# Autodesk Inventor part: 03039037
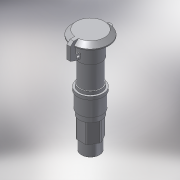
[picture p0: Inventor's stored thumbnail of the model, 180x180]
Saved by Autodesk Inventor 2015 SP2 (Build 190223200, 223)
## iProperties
Created: 2017-06
Part Number: 03039037
Material: PVC-Piping
Description: PLASSON QUICK COUPLING VALVE 3/4"
Document SubType Name: Modeling
Designer: KIM
Mass: 160.732 g
Surface Area: 217.168 cm^2
Volume: 114.809 cm^3
Density: 1.4 g/cm^3
Appearance: Smooth - White
Author: KIM
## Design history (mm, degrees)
derived "03039.ipt"
feature "Solid1::03039.ipt"
tag "TaggingFeature1"
body "Solid1"
other parameters: "d1" = 152, "d23" = 17, "d24" = 45.6, "d25" = 53.2, "d26" = 76, "d27" = 80.56, "d28" = 85.12, "d29" = 118.56, "d32" = 144.4, "d33" = 145.92, "d34" = 26.441, "d40" = 27, "d45" = 31.7292, "d46" = 34.3733, "d47" = 37.0174, "d49" = 29.0851, "d54" = 31.7292, "d55" = 52.882, "d65" = 45 deg, "d66" = 21.1528, "d69" = 0, "d70" = 1.32205, "d73" = 0.52882, "d76" = 7.9323, "d77" = 21.1528, "d78" = 135 deg, "d79" = 110 deg, "d80" = 110 deg, "d81" = 7.9323, "d82" = 2.6441, "d83" = 22.8, "d84" = 5.2882, "d85" = 0, "d86" = 3.96615, "d87" = 10.5764, "d88" = 0, "d89" = 2.6441, "d90" = 2.6441, "d91" = 0, "d92" = 7.9323, "d93" = 1.58646, "d94" = 9.51876, "d95" = 1.32205, "d96" = 0, "R_" = 26.441, "H_" = 152, "l_2" = 17, "d48" = 31.7292
